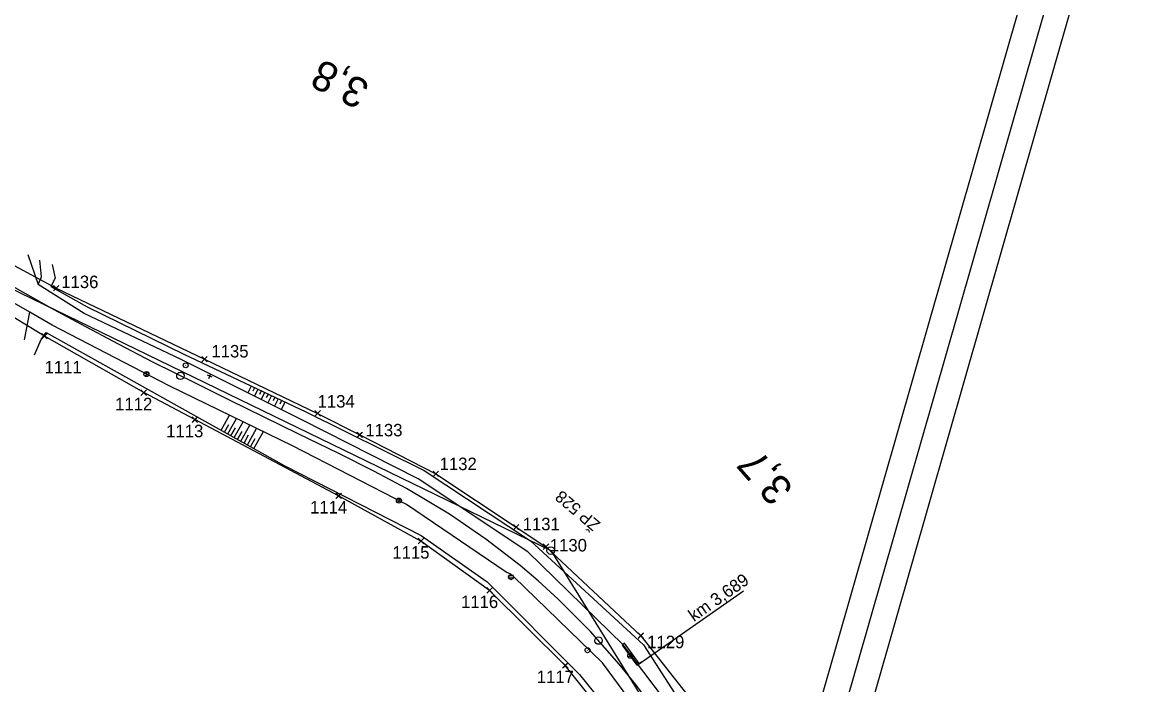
# Model space of a CAD drawing. Extents: x -738085 to -734426, y -1122197 to -1119748.
# Drawn here: x -736950.7 to -736726.4, y -1121615.9 to -1121483.3 of the extents above; entities that cross this region are included whole.
import ezdxf

# ---------------------------------------------------------------- set-up
doc = ezdxf.new("R2010")
doc.units = 0
for name, color, linetype in [('SŽDC', 7, 'Continuous'), ('Vrstva 1', 7, 'Continuous'), ('Vrstva 11', 7, 'Continuous'), ('Vrstva 12', 7, 'Continuous'), ('Vrstva 48', 7, 'Continuous'), ('Vrstva 49', 7, 'Continuous'), ('Vrstva 60', 7, 'Continuous'), ('Vrstva 63', 7, 'Continuous'), ('Vrstva 7', 7, 'Continuous'), ('Vrstva 9', 7, 'Continuous')]:
    doc.layers.add(name, color=color, linetype=linetype)

msp = doc.modelspace()

# ---------------------------------------------------------------- linework, layer by layer
at = {"layer": 'SŽDC'}
for p, q in [((-736977.22, -1121518.54), (-736943.95, -1121536.5)), ((-736946.26, -1121546.1), (-736963.67, -1121535.61)), ((-736943.95, -1121536.5), (-736914.25, -1121550.72)), ((-736887.39, -1121578.1), (-736916.19, -1121562.83)), ((-736883.17, -1121565.89), (-736867.94, -1121573.69)), ((-736867.94, -1121573.69), (-736851.83, -1121584.35)), ((-736870.91, -1121587.14), (-736887.39, -1121578.1)), ((-736857.16, -1121597.03), (-736870.91, -1121587.14)), ((-736842, -1121612.07), (-736857.16, -1121597.03))]:
    msp.add_line(p, q, dxfattribs=at)
for points in [[(-736916.19, -1121562.83), (-736926.41, -1121557.42), (-736946.26, -1121546.1)], [(-736914.25, -1121550.72), (-736891.6, -1121561.57), (-736883.17, -1121565.89)], [(-736851.83, -1121584.35), (-736845.88, -1121588.28), (-736826.87, -1121606.1), (-736816.01, -1121619.92)], [(-736823.69, -1121638.07), (-736831.1, -1121625.74), (-736842, -1121612.07)]]:
    msp.add_lwpolyline(points, dxfattribs=at)
at = {"layer": 'Vrstva 1'}
for points in [[(-736726.43, -1121430.48), (-737533.93, -1121199.12), (-737615.73, -1121484.62), (-736808.23, -1121715.98)], [(-737530.5, -1121205.3), (-736732.61, -1121433.9), (-736811.65, -1121709.79), (-737609.54, -1121481.19)], [(-736738.79, -1121437.33), (-737330, -1121267.94), (-737406.29, -1121534.23), (-736815.08, -1121703.62)]]:
    msp.add_lwpolyline(points, close=True, dxfattribs=at)
msp.add_lwpolyline([(-736824.16, -1121620.98), (-736827.96, -1121615.83), (-736831.21, -1121611.8), (-736836.97, -1121605.25), (-736843.45, -1121598.76), (-736847.45, -1121595.12), (-736851.06, -1121592.07), (-736857.9, -1121586.77), (-736865.18, -1121581.77), (-736873.79, -1121576.65), (-736880.36, -1121573.13), (-736887.36, -1121569.62), (-736895.47, -1121565.67), (-736909.09, -1121558.99), (-736915.79, -1121555.68), (-736924.59, -1121551.29), (-736931.47, -1121547.72), (-736939.01, -1121543.72), (-736944.31, -1121540.84), (-736948.04, -1121538.79), (-736964.17, -1121529.72)], dxfattribs=at)
msp.add_lwpolyline([(-736824.16, -1121620.98), (-736827.96, -1121615.83), (-736831.21, -1121611.8), (-736836.97, -1121605.25), (-736843.45, -1121598.76), (-736847.45, -1121595.12), (-736851.06, -1121592.07), (-736857.9, -1121586.77), (-736865.18, -1121581.77), (-736873.79, -1121576.65), (-736880.36, -1121573.13), (-736887.36, -1121569.62), (-736895.47, -1121565.67), (-736909.09, -1121558.99), (-736915.79, -1121555.68), (-736924.59, -1121551.29), (-736931.47, -1121547.72), (-736939.01, -1121543.72), (-736944.31, -1121540.84), (-736948.04, -1121538.79), (-736964.17, -1121529.72)], dxfattribs=at)
at = {"layer": 'Vrstva 11'}
for p, q in [((-736925.49, -1121553.4), (-736926.37, -1121553.68)), ((-736925.39, -1121553.75), (-736926.26, -1121554.03)), ((-736874.92, -1121578.74), (-736875.81, -1121579.02)), ((-736874.82, -1121579.1), (-736875.69, -1121579.38)), ((-736852.43, -1121594.13), (-736853.36, -1121594.2)), ((-736852.41, -1121594.5), (-736853.32, -1121594.58)), ((-736828.57, -1121610.35), (-736829.47, -1121610.25)), ((-736828.52, -1121609.98), (-736829.44, -1121609.88))]:
    msp.add_line(p, q, dxfattribs=at)
for centre in [(-736925.88, -1121553.71), (-736875.31, -1121579.05), (-736852.88, -1121594.34), (-736829, -1121610.11)]:
    msp.add_circle(centre, 0.5, dxfattribs=at)
at = {"layer": 'Vrstva 12'}
msp.add_lwpolyline([(-736852.93, -1121593.78), (-736852.32, -1121594.3), (-736852.83, -1121594.91), (-736853.44, -1121594.39), (-736852.93, -1121593.78)], dxfattribs=at)
at = {"layer": 'Vrstva 48'}
for p, q in [((-736904.91, -1121556.1), (-736905.56, -1121557.48)), ((-736904.23, -1121556.43), (-736904.56, -1121557.12)), ((-736903.56, -1121556.75), (-736904.22, -1121558.15)), ((-736902.88, -1121557.07), (-736903.22, -1121557.78)), ((-736902.2, -1121557.39), (-736902.88, -1121558.82)), ((-736901.52, -1121557.71), (-736901.87, -1121558.43)), ((-736900.85, -1121558.03), (-736901.54, -1121559.49)), ((-736900.17, -1121558.35), (-736900.52, -1121559.09)), ((-736899.49, -1121558.67), (-736900.2, -1121560.16)), ((-736898.81, -1121559), (-736899.17, -1121559.75)), ((-736898.14, -1121559.32), (-736898.86, -1121560.84)), ((-736910.9, -1121564.96), (-736909.21, -1121561.94)), ((-736909.59, -1121565.69), (-736907.86, -1121562.6)), ((-736910.24, -1121565.32), (-736909.39, -1121563.8)), ((-736908.94, -1121566.06), (-736908.06, -1121564.49)), ((-736908.28, -1121566.42), (-736906.51, -1121563.26)), ((-736907.63, -1121566.79), (-736906.73, -1121565.19)), ((-736906.97, -1121567.16), (-736905.16, -1121563.92)), ((-736905.66, -1121567.89), (-736903.81, -1121564.58)), ((-736904.35, -1121568.62), (-736902.46, -1121565.24)), ((-736906.32, -1121567.52), (-736905.4, -1121565.89)), ((-736905.01, -1121568.26), (-736904.07, -1121566.58))]:
    msp.add_line(p, q, dxfattribs=at)
at = {"layer": 'Vrstva 49'}
for p, q in [((-736949.62, -1121529.79), (-736947.56, -1121535.74)), ((-736950.25, -1121546.82), (-736949.24, -1121541.32))]:
    msp.add_line(p, q, dxfattribs=at)
for points in [[(-736765.34, -1121718.62), (-736768.76, -1121717.41), (-736778.32, -1121705.97), (-736786.95, -1121694.02), (-736800.73, -1121669.8), (-736811.97, -1121646.73), (-736821.95, -1121628.64), (-736834.59, -1121611.55), (-736852.32, -1121594.3), (-736852.93, -1121593.78), (-736853.86, -1121593.36), (-736873.78, -1121579.83), (-736896.64, -1121568.08), (-736921.16, -1121556.11), (-736944.74, -1121543.9), (-736949.24, -1121541.32), (-736966.17, -1121531.65)], [(-736782.58, -1121690.58), (-736795.5, -1121667.44), (-736807.17, -1121644.22), (-736818.23, -1121624.06), (-736830.45, -1121607.96), (-736849.48, -1121589.31), (-736871.46, -1121574.67), (-736894.77, -1121562.88), (-736918.94, -1121550.78), (-736938.32, -1121541.59), (-736947.56, -1121535.74), (-736946.88, -1121534.26), (-736947.22, -1121530.9)], [(-736944.71, -1121531.75), (-736944.12, -1121534.53), (-736945.03, -1121536.18), (-736937.72, -1121540.22), (-736918.35, -1121549.74), (-736893.95, -1121561.3), (-736870.26, -1121573.05), (-736848.96, -1121587.09), (-736826.36, -1121607.95), (-736806.6, -1121638.61), (-736793.5, -1121665.65), (-736784.17, -1121685.72), (-736782.58, -1121690.58)], [(-736948.26, -1121549.88), (-736946.95, -1121546.79), (-736945.91, -1121545.37), (-736898.27, -1121572.03), (-736870.86, -1121586.04), (-736857.62, -1121595.32), (-736839.16, -1121613.89), (-736828.86, -1121626.62), (-736817.85, -1121646.53), (-736804.54, -1121668.5), (-736788.17, -1121694.18), (-736780.03, -1121707.8), (-736773.57, -1121714.47), (-736768.76, -1121717.41)]]:
    msp.add_lwpolyline(points, dxfattribs=at)
at = {"layer": 'Vrstva 60'}
for p, q in [((-736943.5, -1121536.95), (-736944.5, -1121535.95)), ((-736943.5, -1121536.05), (-736944.5, -1121537.05)), ((-736944.4, -1121536.95), (-736943.4, -1121535.95)), ((-736944.4, -1121536.05), (-736943.4, -1121537.05)), ((-736943.95, -1121536.5), (-736943.95, -1121536.5)), ((-736945.81, -1121546.55), (-736946.81, -1121545.55)), ((-736945.81, -1121545.65), (-736946.81, -1121546.65)), ((-736946.71, -1121546.55), (-736945.71, -1121545.55)), ((-736946.71, -1121545.65), (-736945.71, -1121546.65)), ((-736946.26, -1121546.1), (-736946.26, -1121546.1)), ((-736913.8, -1121551.17), (-736914.8, -1121550.17)), ((-736913.8, -1121550.27), (-736914.8, -1121551.27)), ((-736914.7, -1121551.17), (-736913.7, -1121550.17)), ((-736914.7, -1121550.27), (-736913.7, -1121551.27)), ((-736914.25, -1121550.72), (-736914.25, -1121550.72)), ((-736925.96, -1121557.87), (-736926.96, -1121556.87)), ((-736925.96, -1121556.97), (-736926.96, -1121557.97)), ((-736926.86, -1121557.87), (-736925.86, -1121556.87)), ((-736926.86, -1121556.97), (-736925.86, -1121557.97)), ((-736926.41, -1121557.42), (-736926.41, -1121557.42)), ((-736915.74, -1121563.28), (-736916.74, -1121562.28)), ((-736915.74, -1121562.38), (-736916.74, -1121563.38)), ((-736916.64, -1121563.28), (-736915.64, -1121562.28)), ((-736916.64, -1121562.38), (-736915.64, -1121563.38)), ((-736916.19, -1121562.83), (-736916.19, -1121562.83)), ((-736891.15, -1121562.02), (-736892.15, -1121561.02)), ((-736891.15, -1121561.12), (-736892.15, -1121562.12)), ((-736892.05, -1121562.02), (-736891.05, -1121561.02)), ((-736892.05, -1121561.12), (-736891.05, -1121562.12)), ((-736891.6, -1121561.57), (-736891.6, -1121561.57)), ((-736882.72, -1121566.34), (-736883.72, -1121565.34)), ((-736883.62, -1121566.34), (-736882.62, -1121565.34)), ((-736882.72, -1121565.44), (-736883.72, -1121566.44)), ((-736883.62, -1121565.44), (-736882.62, -1121566.44)), ((-736883.17, -1121565.89), (-736883.17, -1121565.89)), ((-736867.49, -1121574.14), (-736868.49, -1121573.14)), ((-736867.49, -1121573.24), (-736868.49, -1121574.24)), ((-736868.39, -1121574.14), (-736867.39, -1121573.14)), ((-736868.39, -1121573.24), (-736867.39, -1121574.24)), ((-736867.94, -1121573.69), (-736867.94, -1121573.69)), ((-736886.94, -1121578.55), (-736887.94, -1121577.55)), ((-736886.94, -1121577.65), (-736887.94, -1121578.65)), ((-736887.84, -1121578.55), (-736886.84, -1121577.55)), ((-736887.84, -1121577.65), (-736886.84, -1121578.65)), ((-736887.39, -1121578.1), (-736887.39, -1121578.1)), ((-736851.38, -1121584.8), (-736852.38, -1121583.8)), ((-736851.38, -1121583.9), (-736852.38, -1121584.9)), ((-736852.28, -1121584.8), (-736851.28, -1121583.8)), ((-736852.28, -1121583.9), (-736851.28, -1121584.9)), ((-736851.83, -1121584.35), (-736851.83, -1121584.35)), ((-736870.46, -1121587.59), (-736871.46, -1121586.59)), ((-736870.46, -1121586.69), (-736871.46, -1121587.69)), ((-736871.36, -1121587.59), (-736870.36, -1121586.59)), ((-736871.36, -1121586.69), (-736870.36, -1121587.69)), ((-736870.91, -1121587.14), (-736870.91, -1121587.14)), ((-736845.43, -1121588.73), (-736846.43, -1121587.73)), ((-736846.33, -1121588.73), (-736845.33, -1121587.73)), ((-736845.43, -1121587.83), (-736846.43, -1121588.83)), ((-736846.33, -1121587.83), (-736845.33, -1121588.83)), ((-736845.88, -1121588.28), (-736845.88, -1121588.28)), ((-736856.71, -1121597.48), (-736857.71, -1121596.48)), ((-736856.71, -1121596.58), (-736857.71, -1121597.58)), ((-736857.61, -1121597.48), (-736856.61, -1121596.48)), ((-736857.61, -1121596.58), (-736856.61, -1121597.58)), ((-736857.16, -1121597.03), (-736857.16, -1121597.03)), ((-736826.42, -1121606.55), (-736827.42, -1121605.55)), ((-736826.42, -1121605.65), (-736827.42, -1121606.65)), ((-736827.32, -1121606.55), (-736826.32, -1121605.55)), ((-736827.32, -1121605.65), (-736826.32, -1121606.65)), ((-736826.87, -1121606.1), (-736826.87, -1121606.1)), ((-736841.55, -1121612.52), (-736842.55, -1121611.52)), ((-736841.55, -1121611.62), (-736842.55, -1121612.62)), ((-736842.45, -1121612.52), (-736841.45, -1121611.52)), ((-736842.45, -1121611.62), (-736841.45, -1121612.62)), ((-736842, -1121612.07), (-736842, -1121612.07))]:
    msp.add_line(p, q, dxfattribs=at)
at = {"layer": 'Vrstva 63'}
for p, q in [((-736981.97, -1121522.48), (-736844.93, -1121589.06)), ((-736844.89, -1121589.09), (-736844.97, -1121589.03)), ((-736844.93, -1121589.06), (-736783.29, -1121688.38))]:
    msp.add_line(p, q, dxfattribs=at)
msp.add_circle((-736844.93, -1121589.06), 0.756, dxfattribs=at)
at = {"layer": 'Vrstva 7'}
for p, q in [((-736917.97, -1121551.98), (-736918.06, -1121551.94)), ((-736912.72, -1121554.35), (-736913.62, -1121553.9)), ((-736913.39, -1121554.57), (-736912.95, -1121553.68)), ((-736837.53, -1121609.04), (-736837.59, -1121608.97))]:
    msp.add_line(p, q, dxfattribs=at)
for centre, radius in [((-736918.01, -1121551.96), 0.5), ((-736919.06, -1121554.05), 0.75), ((-736919.06, -1121554.05), 0.75), ((-736835.36, -1121607.08), 0.75), ((-736835.36, -1121607.08), 0.75), ((-736837.56, -1121609.01), 0.5)]:
    msp.add_circle(centre, radius, dxfattribs=at)
at = {"layer": 'Vrstva 9'}
for p, q in [((-736827.43, -1121611.84), (-736806.31, -1121597.09)), ((-736830.15, -1121607.63), (-736830.64, -1121607.99)), ((-736830.64, -1121607.99), (-736827.67, -1121612.01)), ((-736827.19, -1121611.66), (-736830.15, -1121607.63)), ((-736827.67, -1121612.01), (-736827.19, -1121611.66)), ((-736827.19, -1121611.66), (-736826.7, -1121611.3))]:
    msp.add_line(p, q, dxfattribs=at)

# ---------------------------------------------------------------- texts
at = {"layer": 'Vrstva 60'}
for s, p in [('1136', (-736942.92, -1121536.49)), ('1135', (-736912.86, -1121550.38)), ('1111', (-736946.26, -1121553.57)), ('1112', (-736932.13, -1121560.95)), ('1134', (-736891.6, -1121560.41)), ('1113', (-736921.91, -1121566.36)), ('1133', (-736882.04, -1121566.18)), ('1132', (-736867.17, -1121572.94)), ('1114', (-736893.11, -1121581.63)), ('1131', (-736850.54, -1121584.99)), ('1130', (-736845.11, -1121589.23)), ('1115', (-736876.63, -1121590.67)), ('1116', (-736862.88, -1121600.56)), ('1129', (-736825.61, -1121608.6)), ('1117', (-736847.72, -1121615.6))]:
    msp.add_text(s, height=2.5, dxfattribs=at).set_placement(p)
at = {"layer": 'Vrstva 63'}
msp.add_text('ŽP 528', height=2.4, rotation=139.8121, dxfattribs=at).set_placement((-736834.83, -1121583.52))
at = {"layer": 'Vrstva 7'}
for s, rotation, p in [('3,8', 153.4949, (-736880.84, -1121495.46)), ('3,8', 153.4949, (-736880.84, -1121495.46)), ('3,7', 131.307, (-736796.11, -1121576.55)), ('3,7', 131.307, (-736796.11, -1121576.55))]:
    msp.add_text(s, height=6, rotation=rotation, dxfattribs=at).set_placement(p)
at = {"layer": 'Vrstva 9'}
msp.add_text('km 3,689', height=2.5, rotation=34.9281, dxfattribs=at).set_placement((-736816.26, -1121603.39))

doc.saveas('drawing.dxf')
